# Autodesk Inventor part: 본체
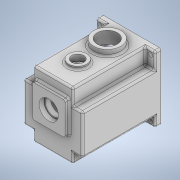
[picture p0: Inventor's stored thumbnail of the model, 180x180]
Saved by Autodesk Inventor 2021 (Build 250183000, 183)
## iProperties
Created: 2022-08
Part Number: 본체
Material: 일반
Document SubType Name: Modeling
Designer: Owner
Density: 1 g/cm^3
Appearance: 기본값
Author: Owner
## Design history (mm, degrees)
sketch "스케치1"
  geometry: L1 (55, 65)-(-55, 65); L2 (-55, 65)-(-55, -65); L3 (-55, -65)-(55, -65); L4 (55, -65)-(55, 65); L5 (55, 65)-(-55, -65); L6 (-55, 65)-(55, -65); 1 further point
  constraints: 12 end point, 2 midpoint, 2 parallel, 1 horizontal, 1 perpendicular
  dimensions: "d0" = 130 distance of L3.end L1.start; "d1" = 110 distance of L2.end L3.end
extrude "돌출1" new body sketch "스케치1" stored distance "d2" = 98; taper "d3" = 0 deg
sketch "스케치3"
  geometry: L1 (0, 0)-(0, 130) reference; L2 (0, 0)-(98, 0) reference; L3 (0, 120)-(16, 120); L4 (16, 120)-(16, 0); L5 (16, 0)-(0, 0); L6 (0, 0)-(0, 120); L7 (0, 130)-(98, 130) reference; L8 (49, 130)-(49, 0); L9 (82, 120)-(82, 0); L10 (98, 120)-(82, 120); L11 (98, 0)-(98, 130); L12 (98, 0)-(0, 0); 3 further points
  constraints: 18 end point, 5 symmetric about line, 4 point on line, 2 midpoint, 2 parallel, 1 horizontal, 1 perpendicular
  dimensions: "d9" = 16 distance of L3.start L3.end; "d10" = 10 distance between parallel lines of L7 L3
extrude "돌출3" cut sketch "스케치3" distance "d11" = 27; taper "d12" = 0 deg
sketch "스케치4"
  geometry: L1 (98, 10)-(98, 130) reference; L2 (98, 130)-(0, 130) reference; L3 (98, 10)-(82, 10); L4 (82, 10)-(82, 130); L5 (82, 130)-(98, 130); L6 (98, 130)-(98, 10); L7 (0, 0)-(98, 0) reference; L8 (49, 0)-(49, 130); L9 (16, 10)-(16, 130); L10 (0, 10)-(16, 10); L11 (0, 10)-(0, 130); L12 (0, 130)-(98, 130); 3 further points
  constraints: 18 end point, 5 symmetric about line, 2 midpoint, 2 parallel, 2 point on line, 1 horizontal, 1 perpendicular
  dimensions: "d13" = 16 distance of L1.start L3.end
extrude "돌출4" cut sketch "스케치4" distance "d14" = 17; taper "d15" = 0 deg
sketch "스케치5"
  geometry: L1 (6, -17)-(60, -17); L2 (60, -17)-(60, -71); L3 (60, -71)-(6, -71); L4 (6, -71)-(6, -17); L5 (6, -17)-(60, -71); L6 (60, -17)-(6, -71); L7 (0, 0)-(66, 0) reference; 3 further points
  constraints: 12 end point, 4 midpoint, 2 parallel, 1 horizontal, 1 perpendicular, 1 vertical alignment
  dimensions: "d16" = 54 distance of L1.end L2.end; "d17" = 54 distance of L1.start L1.end; "d88" = 44 distance from line of point (33, -44) L7
extrude "돌출5" join sketch "스케치5" distance "d18" = 7; taper "d19" = 0 deg
fillet "모깎기1" dims "d20" = 3
fillet "모깎기2" dims "d21" = 3
fillet "모깎기3" dims "d22" = 3
fillet "모깎기4" dims "d23" = 3
fillet "모깎기5" dims "d24" = 3
sketch "스케치6"
  geometry: L1 (0, -110)-(0, 0) reference; L2 (0, -55)-(98, -55); L3 (98, 0)-(98, -110) reference; L4 (98, 0)-(0, 0) reference; C1 r 3.5 at (7, -7); C2 r 3.5 at (91, -7); C3 r 3.5 at (7, -103); C4 r 3.5 at (91, -103); 1 further point
  constraints: 4 centre point, 2 end point, 2 midpoint, 2 symmetric about line, 2 other
  dimensions: "d25" = 7 distance from line of L4 C1.centre; "d26" = 7 distance from line of C1.centre L1; "d27" = 84 distance of C2.centre C1.centre; "d28" = 7 distance from line of L4 C2.centre; "d29" = 7 diameter of C1; "d30" = 7 diameter of C2
extrude "돌출6" cut sketch "스케치6" distance "d31" = 10; taper "d32" = 0 deg
fillet "모깎기6" dims "d33" = 3
fillet "모깎기7" dims "d34" = 3
sketch "스케치7"
  geometry: L1 (57, -17)-(9, -17) reference; C1 r 14 at (33, -44); 2 further points
  constraints: 1 centre point, 1 coincident, 1 midpoint, 1 vertical alignment
  dimensions: "d35" = 28 diameter of C1; "d90" = 27 distance from line of L1 point (33, -44)
extrude "돌출7" cut sketch "스케치7" extent not by distance; stored distance "d36" = 10; taper "d37" = 0 deg
sketch "스케치8"
  geometry: L1 (57, -17)-(9, -17) reference; C1 r 16 at (33, -44); 2 further points
  constraints: 1 centre point, 1 coincident, 1 midpoint, 1 vertical alignment
  dimensions: "d38" = 32 diameter of C1; "d89" = 27 distance from line of L1 point (33, -44)
extrude "돌출8" cut sketch "스케치8" distance "d39" = 8.3; taper "d40" = 0 deg
fillet "모깎기8" dims "d44" = 0.3
sketch "스케치9"
  geometry: L1 (23, -10)-(69, -10); L2 (23, -10)-(23, -24.857); L3 (69, -10)-(69, -24.857); L4 (92, 0)-(0, 0) reference; L5 (92, -110)-(0, -110) reference; A1 r 42 centre (46, -60) between (23, -24.857) and (69, -24.857); 3 further points
  constraints: 6 end point, 2 midpoint, 2 point on circle, 2 vertical, 2 vertical alignment, 1 centre point, 1 horizontal
  dimensions: "d46" = 42 radius of A1; "d47" = 46 distance of L1.start L1.end; "d48" = 50 distance from line of A1.centre L1; "d49" = 50 distance from line of L5 A1.centre
extrude "돌출9" cut sketch "스케치9" distance "d50" = 120; taper "d51" = 0 deg
sketch "스케치10"
  geometry: L1 (23, -24.857)-(23, -10) reference; L2 (23, -10)-(69, -10) reference; L3 (69, -10)-(69, -24.857) reference; L4 (72, -7)-(20, -7); L5 (20, -7)-(20, -23.271); L6 (72, -23.271)-(72, -7); A1 r 42 centre (46, -60) between (23, -24.857) and (69, -24.857) reference; A2 r 45 centre (46, -60) between (20, -23.271) and (72, -23.271); 1 further point
  constraints: 6 end point, 2 point on circle, 1 centre point, 3 other
  dimensions: "d52" = 3 distance between parallel lines of L4 L2
extrude "돌출10" cut sketch "스케치10" distance "d53" = 9; taper "d54" = 0 deg
fillet "모깎기9" dims "d55" = 6
fillet "모깎기10" dims "d56" = 3
fillet "모깎기11" dims "d57" = 3
chamfer "모따기2" distance "d58" = 1; stored, may be unused: second distance "d59" = 2, angle "d60" = 30 deg
sketch "스케치11"
  geometry: L1 (-16, 127)-(76, 127) reference; C1 r 15 at (30, 38); 1 further point
  constraints: 1 centre point, 1 vertical alignment
  dimensions: "d62" = 30 diameter of C1; "d63" = 89 distance from line of L1 C1.centre
extrude "돌출11" join sketch "스케치11" distance "d64" = 5; taper "d65" = 0 deg
sketch "스케치12"
  geometry: L1 (-16, 127)-(76, 127) reference; C1 r 22.5 at (30, 87); 1 further point
  constraints: 1 centre point, 1 vertical alignment
  dimensions: "d66" = 45 diameter of C1; "d67" = 40 distance from line of L1 C1.centre
extrude "돌출12" join sketch "스케치12" distance "d68" = 10; taper "d69" = 0 deg
sketch "스케치13"
  geometry: C1 r 22.5 at (0, 0) reference; 2 further points
  constraints: 1 coincident
hole "구멍1" sketch "스케치13" at (0, 0) diameter "d70" = 33.376; stored, may be unused: countersink angle "d74" = 90 deg, drill point angle "d76" = 118 deg; dims "d71" = 70, "d72" = 4, "d73" = 2, "d75" = 77.3
sketch "스케치14"
  geometry: C1 r 10 at (0, 0); C2 r 15 at (0, 0) reference; 1 further point
  constraints: 1 centre point, 1 coincident, 1 vertical alignment
  dimensions: "d77" = 20 diameter of C1
extrude "돌출13" cut sketch "스케치14" distance "d78" = 30; taper "d79" = 0 deg
sketch "스케치15"
  geometry: C1 r 10 at (20, 80) reference; C2 r 15 at (20, 80); 1 further point
  constraints: 1 centre point, 1 coincident
  dimensions: "d80" = 30 diameter of C2
extrude "돌출14" cut sketch "스케치15" distance "d81" = 5; taper "d82" = 0 deg
chamfer "모따기3" distance "d83" = 1; stored, may be unused: second distance "d84" = 2, angle "d85" = 30 deg
fillet "모깎기12" dims "d86" = 3
sketch "스케치16"
  geometry: 1 further point
sketch "스케치19"
  geometry: A1 r 15 centre (46, -75) between (37.022, -62.984) and (54.978, -62.984); A2 r 21 centre (46, -44) between (54.978, -62.984) and (37.022, -62.984); 1 further point
  constraints: 4 point on circle, 2 centre point, 2 vertical alignment
  dimensions: "d91" = 20 distance of point (46, -55) A1.centre; "d92" = 30 diameter of A1; "d93" = 11 distance of point (46, -55) A2.centre; "d94" = 42 diameter of A2
extrude "돌출15" join sketch "스케치19" distance "d95" = 10; taper "d96" = 0 deg
fillet "모깎기13" dims "d97" = 3
fillet "모깎기14" dims "d98" = 3
sketch "스케치20"
  geometry: L1 (65, 35)-(65, 52) reference; L2 (62, 55)-(-58, 55) reference; 2 further points
  constraints: 1 other
  dimensions: "d99" = 65 distance from line of L1 point (0, -5); "d100" = 60 distance from line of L2 point (0, -5)
feature "엠보싱1" sketch "스케치20" dims "d101" = 0.5, "d102" = 0
node "솔리드1"
node "투영된 루프1"
